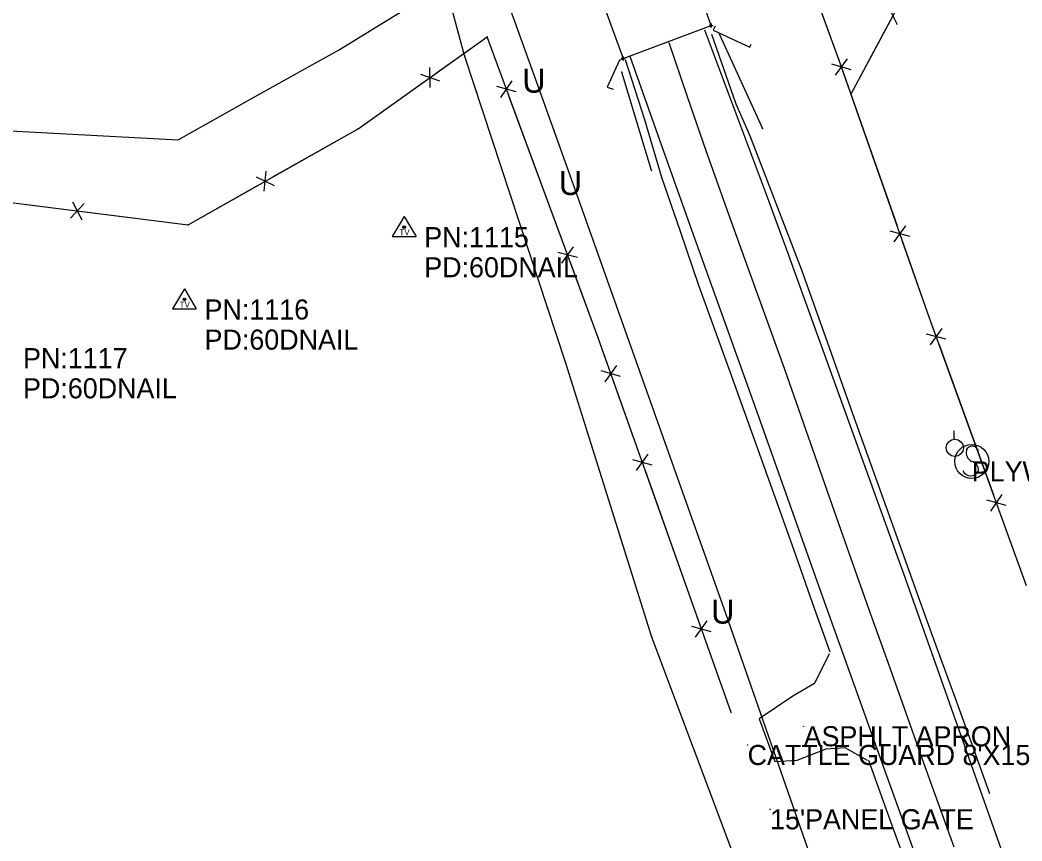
# Model space of a CAD drawing. Extents: x 1050807 to 1053552, y 395828 to 398415.
# Drawn here: x 1052065.9 to 1052315.2, y 397198.7 to 397403.1 of the extents above; entities that cross this region are included whole.
import ezdxf

# ---------------------------------------------------------------- set-up
doc = ezdxf.new("R2010")
doc.units = 0
for name, color, linetype in [('Default', 7, 'Continuous'), ('S_BRIDGE', 7, 'Continuous'), ('S_DITCHLINE', 7, 'Continuous'), ('S_EDGE_CONCRETE', 7, 'Continuous'), ('S_EDGE_PAVEMENT', 7, 'Continuous'), ('S_FENCE', 7, 'Continuous'), ('S_GUARDRAIL', 7, 'Continuous'), ('S_MISC_STRUCTURES_ANNOT', 7, 'Continuous'), ('S_MSC_PT_SYM', 7, 'Continuous'), ('S_PAVEMENT_CROWN', 7, 'Continuous'), ('S_RDW_PT_SYM', 7, 'Continuous'), ('S_SECONDARY_CTL', 7, 'Continuous'), ('S_SECONDARY_CTL_ANNOT', 7, 'Continuous'), ('S_SHOULDER', 7, 'Continuous'), ('S_SIGN', 7, 'Continuous'), ('S_SIGN_ANNOT', 7, 'Continuous'), ('S_STR_PT_SYM', 7, 'Continuous'), ('S_SURVEY_TEXT_ANNOT', 7, 'Continuous'), ('S_UNDERGROUND_CABLE', 7, 'Continuous'), ('S_UTILITY_POLE', 7, 'Continuous'), ('S_UTL_PT_SYM', 7, 'Continuous'), ('S_WATER_UTILITIES', 7, 'Continuous')]:
    doc.layers.add(name, color=color, linetype=linetype)

msp = doc.modelspace()

# ---------------------------------------------------------------- linework, layer by layer
at = {"layer": 'S_BRIDGE'}
for p, q in [((1052237.9, 397401.73), (1052216.82, 397461.36)), ((1052194.17, 397453.08), (1052216.01, 397393.51)), ((1052216.01, 397393.51), (1052237.9, 397401.73))]:
    msp.add_line(p, q, dxfattribs=at)
at = {"layer": 'S_DITCHLINE'}
msp.add_lwpolyline([(1051923.97, 397264.82), (1051934.15, 397286.32), (1051944.33, 397307.83), (1051958.22, 397321.57), (1051972.1, 397335.31), (1051985.98, 397349.06), (1051999.87, 397362.8), (1052014.51, 397368.54), (1052029.14, 397374.28), (1052043.96, 397375.01), (1052058.77, 397375.75), (1052082, 397374.5), (1052105.23, 397373.25), (1052125.17, 397384.42), (1052145.11, 397395.59), (1052158.93, 397404.03), (1052172.75, 397412.47), (1052180.81, 397417.01)], dxfattribs=at)
at = {"layer": 'S_EDGE_CONCRETE'}
for points in [[(1052238.84, 397401.57), (1052238.36, 397400.54), (1052247.51, 397396.34), (1052247.82, 397397.09)], [(1052215.81, 397393.22), (1052215.05, 397393.1), (1052211.96, 397386.34), (1052213.47, 397385.89)]]:
    msp.add_lwpolyline(points, dxfattribs=at)
at = {"layer": 'S_EDGE_PAVEMENT'}
for points in [[(1052366.56, 397036.55), (1052362.3, 397048.53), (1052358.05, 397060.51), (1052353.79, 397072.49), (1052349.54, 397084.47), (1052341.79, 397106.52), (1052334.05, 397128.57), (1052326.07, 397151.2), (1052318.09, 397173.83), (1052310.11, 397196.56), (1052302.13, 397219.28), (1052294.23, 397241.56), (1052286.33, 397263.84), (1052278.39, 397285.89), (1052270.44, 397307.95), (1052265.77, 397320.81), (1052261.1, 397333.67), (1052256.44, 397346.52), (1052251.77, 397359.38), (1052244.05, 397379.98), (1052236.34, 397400.57)], [(1052358.04, 397002.59), (1052353.03, 397016.23), (1052348.02, 397029.87), (1052339.76, 397052.84), (1052331.5, 397075.82), (1052327.24, 397087.68), (1052322.99, 397099.53), (1052318.74, 397111.39), (1052314.49, 397123.25), (1052310.27, 397135.03), (1052306.04, 397146.82), (1052301.81, 397158.61), (1052297.59, 397170.39), (1052289.45, 397193.11), (1052281.31, 397215.83), (1052273.5, 397237.65), (1052265.69, 397259.46), (1052257.46, 397282.59), (1052249.24, 397305.71), (1052241.37, 397327.67), (1052233.5, 397349.63), (1052225.59, 397371.79), (1052217.68, 397393.96)], [(1052267.22, 397245.36), (1052263.6, 397237.92), (1052258.19, 397234.78), (1052249.86, 397229.17), (1052253.74, 397218.52), (1052259.32, 397218.89), (1052266.54, 397221.66), (1052271.16, 397222.05), (1052276.68, 397218.89)]]:
    msp.add_lwpolyline(points, dxfattribs=at)
at = {"layer": 'S_FENCE'}
for p, q in [((1052272.73, 397384.71), (1052296.55, 397429.15)), ((1052269.65, 397393.29), (1052257.06, 397427.76)), ((1052284.25, 397401.87), (1052282, 397406.33)), ((1052284.25, 397401.87), (1052282, 397406.33)), ((1052149.99, 397375.99), (1052182.1, 397398.92)), ((1052209.78, 397323.97), (1052182.1, 397398.91)), ((1052268.86, 397389.35), (1052271.78, 397393.41)), ((1052268.86, 397389.35), (1052271.78, 397393.41)), ((1052292.16, 397329.1), (1052269.65, 397393.29)), ((1052167.92, 397386.27), (1052167.87, 397391.27)), ((1052167.92, 397386.27), (1052167.87, 397391.27)), ((1052272.73, 397390.71), (1052267.91, 397392.06)), ((1052272.73, 397390.71), (1052267.91, 397392.06)), ((1052165.54, 397389.61), (1052170.25, 397387.94)), ((1052165.54, 397389.61), (1052170.25, 397387.94)), ((1052189.33, 397385.23), (1052184.5, 397386.5)), ((1052189.33, 397385.23), (1052184.5, 397386.5)), ((1052185.49, 397383.81), (1052188.34, 397387.92)), ((1052185.49, 397383.81), (1052188.34, 397387.92)), ((1052107.7, 397352.14), (1052149.99, 397375.99)), ((1052124.61, 397364.03), (1052129.12, 397361.87)), ((1052124.61, 397364.03), (1052129.12, 397361.87)), ((1052126.62, 397360.46), (1052127.11, 397365.43)), ((1052126.62, 397360.46), (1052127.11, 397365.43)), ((1052058.28, 397358.31), (1052107.7, 397352.14)), ((1052078.43, 397353.73), (1052081.79, 397357.44)), ((1052078.43, 397353.73), (1052081.79, 397357.44)), ((1052078.94, 397357.8), (1052081.28, 397353.38)), ((1052078.94, 397357.8), (1052081.28, 397353.38)), ((1052283.42, 397347.83), (1052286.34, 397351.89)), ((1052283.42, 397347.83), (1052286.34, 397351.89)), ((1052287.29, 397349.19), (1052282.47, 397350.54)), ((1052287.29, 397349.19), (1052282.47, 397350.54)), ((1052200.73, 397342.55), (1052203.58, 397346.65)), ((1052200.73, 397342.55), (1052203.58, 397346.65)), ((1052204.57, 397343.96), (1052199.74, 397345.23)), ((1052204.57, 397343.96), (1052199.74, 397345.23)), ((1052316.4, 397262.22), (1052292.16, 397329.1)), ((1052292.47, 397322.23), (1052295.35, 397326.32)), ((1052292.47, 397322.23), (1052295.35, 397326.32)), ((1052242.82, 397230.76), (1052209.78, 397323.97)), ((1052296.32, 397323.62), (1052291.5, 397324.92)), ((1052296.32, 397323.62), (1052291.5, 397324.92)), ((1052215.35, 397314.38), (1052210.53, 397315.72)), ((1052215.35, 397314.38), (1052210.53, 397315.72)), ((1052211.49, 397313.01), (1052214.39, 397317.08)), ((1052211.49, 397313.01), (1052214.39, 397317.08)), ((1052223.18, 397292.29), (1052218.36, 397293.63)), ((1052223.18, 397292.29), (1052218.36, 397293.63)), ((1052219.32, 397290.93), (1052222.22, 397295)), ((1052219.32, 397290.93), (1052222.22, 397295)), ((1052311.32, 397282.25), (1052306.49, 397283.55)), ((1052311.32, 397282.25), (1052306.49, 397283.55)), ((1052307.47, 397280.86), (1052310.34, 397284.95)), ((1052307.47, 397280.86), (1052310.34, 397284.95)), ((1052234.02, 397249.45), (1052236.92, 397253.53)), ((1052234.02, 397249.45), (1052236.92, 397253.53)), ((1052237.88, 397250.82), (1052233.06, 397252.16)), ((1052237.88, 397250.82), (1052233.06, 397252.16))]:
    msp.add_line(p, q, dxfattribs=at)
for points in [[(1052269.65, 397393.29), (1052262.82, 397411.99)], [(1052269.65, 397393.29), (1052262.82, 397411.99)], [(1052272.73, 397384.71), (1052282.18, 397402.34)], [(1052272.73, 397384.71), (1052282.18, 397402.34)], [(1052169.52, 397389.94), (1052182.1, 397398.92)], [(1052169.52, 397389.94), (1052182.1, 397398.92)], [(1052186.42, 397387.21), (1052182.1, 397398.91)], [(1052186.42, 397387.21), (1052182.1, 397398.91)], [(1052269.85, 397392.74), (1052269.65, 397393.29)], [(1052269.85, 397392.74), (1052269.65, 397393.29)], [(1052284.22, 397351.75), (1052270.98, 397389.5)], [(1052284.22, 397351.75), (1052270.98, 397389.5)], [(1052149.99, 397375.99), (1052166.27, 397387.61)], [(1052149.99, 397375.99), (1052166.27, 397387.61)], [(1052201.46, 397346.48), (1052187.61, 397383.99)], [(1052201.46, 397346.48), (1052187.61, 397383.99)], [(1052128.6, 397363.93), (1052149.99, 397375.99)], [(1052128.6, 397363.93), (1052149.99, 397375.99)], [(1052107.7, 397352.14), (1052125.12, 397361.96)], [(1052107.7, 397352.14), (1052125.12, 397361.96)], [(1052058.28, 397358.31), (1052078.13, 397355.83)], [(1052058.28, 397358.31), (1052078.13, 397355.83)], [(1052082.09, 397355.34), (1052107.7, 397352.14)], [(1052082.09, 397355.34), (1052107.7, 397352.14)], [(1052292.16, 397329.1), (1052285.54, 397347.97)], [(1052292.16, 397329.1), (1052285.54, 397347.97)], [(1052209.78, 397323.97), (1052202.85, 397342.72)], [(1052209.78, 397323.97), (1052202.85, 397342.72)], [(1052293.42, 397325.62), (1052292.16, 397329.1)], [(1052293.42, 397325.62), (1052292.16, 397329.1)], [(1052212.27, 397316.93), (1052209.78, 397323.97)], [(1052212.27, 397316.93), (1052209.78, 397323.97)], [(1052308.22, 397284.78), (1052294.59, 397322.39)], [(1052308.22, 397284.78), (1052294.59, 397322.39)], [(1052220.29, 397294.31), (1052213.61, 397313.16)], [(1052220.29, 397294.31), (1052213.61, 397313.16)], [(1052234.8, 397253.38), (1052221.44, 397291.08)], [(1052234.8, 397253.38), (1052221.44, 397291.08)], [(1052316.4, 397262.22), (1052309.58, 397281.02)], [(1052316.4, 397262.22), (1052309.58, 397281.02)], [(1052242.82, 397230.76), (1052236.14, 397249.61)], [(1052242.82, 397230.76), (1052236.14, 397249.61)]]:
    msp.add_lwpolyline(points, dxfattribs=at)
at = {"layer": 'S_GUARDRAIL'}
for p, q in [((1052239.93, 397399.47), (1052250.68, 397376.05)), ((1052223.07, 397365.6), (1052215.65, 397390.1))]:
    msp.add_line(p, q, dxfattribs=at)
at = {"layer": 'S_MSC_PT_SYM'}
for points in [[(1052182.1, 397398.92), (1052182.1, 397398.97), (1052182.1, 397398.92), (1052182.05, 397398.92), (1052182.1, 397398.92), (1052182.1, 397398.87), (1052182.1, 397398.92), (1052182.15, 397398.92)], [(1052182.1, 397398.91), (1052182.1, 397398.96), (1052182.1, 397398.91), (1052182.05, 397398.91), (1052182.1, 397398.91), (1052182.1, 397398.86), (1052182.1, 397398.91), (1052182.15, 397398.91)], [(1052269.65, 397393.29), (1052269.65, 397393.34), (1052269.65, 397393.29), (1052269.6, 397393.29), (1052269.65, 397393.29), (1052269.65, 397393.24), (1052269.65, 397393.29), (1052269.7, 397393.29)], [(1052272.73, 397384.71), (1052272.73, 397384.76), (1052272.73, 397384.71), (1052272.68, 397384.71), (1052272.73, 397384.71), (1052272.73, 397384.66), (1052272.73, 397384.71), (1052272.78, 397384.71)], [(1052149.99, 397375.99), (1052149.99, 397376.04), (1052149.99, 397375.99), (1052149.94, 397375.99), (1052149.99, 397375.99), (1052149.99, 397375.94), (1052149.99, 397375.99), (1052150.04, 397375.99)], [(1052107.7, 397352.14), (1052107.7, 397352.19), (1052107.7, 397352.14), (1052107.65, 397352.14), (1052107.7, 397352.14), (1052107.7, 397352.09), (1052107.7, 397352.14), (1052107.75, 397352.14)], [(1052292.16, 397329.1), (1052292.16, 397329.15), (1052292.16, 397329.1), (1052292.11, 397329.1), (1052292.16, 397329.1), (1052292.16, 397329.05), (1052292.16, 397329.1), (1052292.21, 397329.1)], [(1052209.78, 397323.97), (1052209.78, 397324.02), (1052209.78, 397323.97), (1052209.73, 397323.97), (1052209.78, 397323.97), (1052209.78, 397323.92), (1052209.78, 397323.97), (1052209.83, 397323.97)], [(1052242.82, 397230.76), (1052242.82, 397230.81), (1052242.82, 397230.76), (1052242.77, 397230.76), (1052242.82, 397230.76), (1052242.82, 397230.71), (1052242.82, 397230.76), (1052242.87, 397230.76)], [(1052260.89, 397227.31), (1052260.89, 397227.36), (1052260.89, 397227.31), (1052260.84, 397227.31), (1052260.89, 397227.31), (1052260.89, 397227.26), (1052260.89, 397227.31), (1052260.94, 397227.31)], [(1052246.95, 397222.65), (1052246.95, 397222.7), (1052246.95, 397222.65), (1052246.9, 397222.65), (1052246.95, 397222.65), (1052246.95, 397222.6), (1052246.95, 397222.65), (1052247, 397222.65)], [(1052252.55, 397206.64), (1052252.55, 397206.69), (1052252.55, 397206.64), (1052252.5, 397206.64), (1052252.55, 397206.64), (1052252.55, 397206.59), (1052252.55, 397206.64), (1052252.6, 397206.64)]]:
    msp.add_lwpolyline(points, dxfattribs=at)
at = {"layer": 'S_PAVEMENT_CROWN'}
msp.add_lwpolyline([(1052298.35, 397197.17), (1052290.41, 397219.3), (1052285.99, 397231.71), (1052281.56, 397244.12), (1052277.14, 397256.52), (1052272.71, 397268.93), (1052268.57, 397280.78), (1052264.42, 397292.63), (1052260.27, 397304.48), (1052256.12, 397316.32), (1052251.24, 397329.87), (1052246.36, 397343.42), (1052241.48, 397356.98), (1052236.6, 397370.53), (1052232.03, 397383.98), (1052227.45, 397397.43)], dxfattribs=at)
at = {"layer": 'S_RDW_PT_SYM'}
for points in [[(1052239.93, 397399.47), (1052239.93, 397399.52), (1052239.93, 397399.47), (1052239.88, 397399.47), (1052239.93, 397399.47), (1052239.93, 397399.42), (1052239.93, 397399.47), (1052239.98, 397399.47)], [(1052215.65, 397390.1), (1052215.65, 397390.15), (1052215.65, 397390.1), (1052215.6, 397390.1), (1052215.65, 397390.1), (1052215.65, 397390.05), (1052215.65, 397390.1), (1052215.7, 397390.1)], [(1052250.68, 397376.05), (1052250.68, 397376.1), (1052250.68, 397376.05), (1052250.63, 397376.05), (1052250.68, 397376.05), (1052250.68, 397376), (1052250.68, 397376.05), (1052250.73, 397376.05)], [(1052223.07, 397365.6), (1052223.07, 397365.65), (1052223.07, 397365.6), (1052223.02, 397365.6), (1052223.07, 397365.6), (1052223.07, 397365.55), (1052223.07, 397365.6), (1052223.12, 397365.6)]]:
    msp.add_lwpolyline(points, dxfattribs=at)
at = {"layer": 'S_SECONDARY_CTL'}
for p, q in [((1052161.47, 397354.14), (1052158.46, 397349.19)), ((1052161.47, 397354.14), (1052164.42, 397349.19)), ((1052158.46, 397349.19), (1052164.42, 397349.19)), ((1052106.79, 397336.14), (1052103.78, 397331.18)), ((1052106.79, 397336.14), (1052109.74, 397331.18)), ((1052103.78, 397331.18), (1052109.74, 397331.18))]:
    msp.add_line(p, q, dxfattribs=at)
for centre, radius in [((1052161.47, 397351.53), 0.311), ((1052161.47, 397351.53), 0.183), ((1052161.47, 397351.53), 0.103), ((1052106.79, 397333.53), 0.311), ((1052106.79, 397333.53), 0.183), ((1052106.79, 397333.53), 0.103)]:
    msp.add_circle(centre, radius, dxfattribs=at)
at = {"layer": 'S_SHOULDER'}
for points in [[(1052307.23, 397210.49), (1052302.9, 397222.47), (1052298.58, 397234.44), (1052294.25, 397246.42), (1052289.93, 397258.39), (1052281.55, 397281.71), (1052273.18, 397305.02), (1052266.82, 397322.9), (1052260.47, 397340.79), (1052254.07, 397357.38), (1052247.67, 397373.97), (1052244.1, 397382.17), (1052238.02, 397399.51)], [(1052267.49, 397245.72), (1052263.21, 397257.8), (1052258.93, 397269.88), (1052254.65, 397281.96), (1052250.36, 397294.03), (1052242.59, 397315.53), (1052234.82, 397337.03), (1052230.23, 397350.44), (1052225.63, 397363.86), (1052221.38, 397378.22), (1052216.55, 397393.14)], [(1052355.65, 397004.17), (1052350.97, 397016.49), (1052346.3, 397028.81), (1052337.6, 397052.24), (1052328.9, 397075.66), (1052324.34, 397088.12), (1052319.79, 397100.59), (1052315.23, 397113.05), (1052310.67, 397125.51), (1052302.75, 397147.54), (1052294.83, 397169.57), (1052290.39, 397181.87), (1052285.96, 397194.16), (1052281.52, 397206.46), (1052277.09, 397218.75)]]:
    msp.add_lwpolyline(points, dxfattribs=at)
at = {"layer": 'S_SIGN'}
msp.add_circle((1052302.74, 397293.22), 4.24, dxfattribs=at)
for centre, radius, start, end in [((1052303.9, 397295.48), 2.55, 167.1196, 241.9813), ((1052302.86, 397295.38), 1.62, 16.5258, 156.8957), ((1052302.48, 397291.82), 2.17, 204.641, 335.359), ((1052302.04, 397290.94), 2.38, 358.6529, 73.7063)]:
    msp.add_arc(centre, radius, start, end, dxfattribs=at)
at = {"layer": 'S_STR_PT_SYM'}
for points in [[(1052237.9, 397401.73), (1052237.9, 397402.23), (1052237.9, 397401.73), (1052237.4, 397401.73), (1052237.9, 397401.73), (1052237.9, 397401.23), (1052237.9, 397401.73), (1052238.4, 397401.73)], [(1052216.01, 397393.51), (1052216.01, 397394.01), (1052216.01, 397393.51), (1052215.51, 397393.51), (1052216.01, 397393.51), (1052216.01, 397393.01), (1052216.01, 397393.51), (1052216.51, 397393.51)]]:
    msp.add_lwpolyline(points, dxfattribs=at)
at = {"layer": 'S_UNDERGROUND_CABLE'}
for p, q in [((1052194.51, 397387.53), (1052172.07, 397449.89)), ((1052203.58, 397362.07), (1052194.51, 397387.53)), ((1052241.5, 397255.38), (1052203.58, 397362.07)), ((1052273.7, 397163.31), (1052241.5, 397255.38))]:
    msp.add_line(p, q, dxfattribs=at)
at = {"layer": 'S_UTILITY_POLE'}
msp.add_line((1052298.4, 397298.73), (1052298.4, 397300.84), dxfattribs=at)
msp.add_circle((1052298.52, 397296.59), 2.13, dxfattribs=at)
at = {"layer": 'S_UTL_PT_SYM'}
for points in [[(1052176.5, 397394.27), (1052176.5, 397394.32), (1052176.5, 397394.27), (1052176.45, 397394.27), (1052176.5, 397394.27), (1052176.5, 397394.22), (1052176.5, 397394.27), (1052176.55, 397394.27)], [(1052201.72, 397317.67), (1052201.72, 397317.72), (1052201.72, 397317.67), (1052201.67, 397317.67), (1052201.72, 397317.67), (1052201.72, 397317.62), (1052201.72, 397317.67), (1052201.77, 397317.67)], [(1052223.15, 397249.48), (1052223.15, 397249.53), (1052223.15, 397249.48), (1052223.1, 397249.48), (1052223.15, 397249.48), (1052223.15, 397249.43), (1052223.15, 397249.48), (1052223.2, 397249.48)]]:
    msp.add_lwpolyline(points, dxfattribs=at)
at = {"layer": 'S_WATER_UTILITIES'}
for p, q in [((1052176.5, 397394.27), (1052163.71, 397441.57)), ((1052201.72, 397317.67), (1052176.5, 397394.27)), ((1052223.15, 397249.48), (1052201.72, 397317.67)), ((1052244.07, 397193.55), (1052223.15, 397249.48))]:
    msp.add_line(p, q, dxfattribs=at)

# ---------------------------------------------------------------- texts
at = {"layer": 'Default'}
for p in [(1052190.88, 397384.98), (1052199.95, 397359.52), (1052237.87, 397252.84)]:
    msp.add_text('U', height=6, dxfattribs=at).set_placement(p)
at = {"layer": 'S_MISC_STRUCTURES_ANNOT'}
msp.add_text('CATTLE GUARD 8\'X15\'6"', height=5, dxfattribs=at).set_placement((1052246.95, 397217.65))
at = {"layer": 'S_SECONDARY_CTL'}
for p in [(1052160.27, 397349.52), (1052105.59, 397331.51)]:
    msp.add_text('TV', height=1.5, dxfattribs=at).set_placement(p)
at = {"layer": 'S_SECONDARY_CTL_ANNOT'}
for s, p in [('PN:1115', (1052166.47, 397346.53)), ('PD:60DNAIL', (1052166.47, 397339.03)), ('PN:1116', (1052111.79, 397328.53)), ('PD:60DNAIL', (1052111.79, 397321.03)), ('PN:1117', (1052066.61, 397316.41)), ('PD:60DNAIL', (1052066.61, 397308.91))]:
    msp.add_text(s, height=5, dxfattribs=at).set_placement(p)
at = {"layer": 'S_SIGN_ANNOT'}
msp.add_text('PLYWOOD WELCOME TO APPLETON SIGN', height=5, dxfattribs=at).set_placement((1052302.74, 397288.22))
at = {"layer": 'S_SURVEY_TEXT_ANNOT'}
for s, p in [('ASPHLT APRON', (1052260.89, 397222.31)), ("15'PANEL GATE", (1052252.55, 397201.64))]:
    msp.add_text(s, height=5, dxfattribs=at).set_placement(p)

doc.saveas('drawing.dxf')
